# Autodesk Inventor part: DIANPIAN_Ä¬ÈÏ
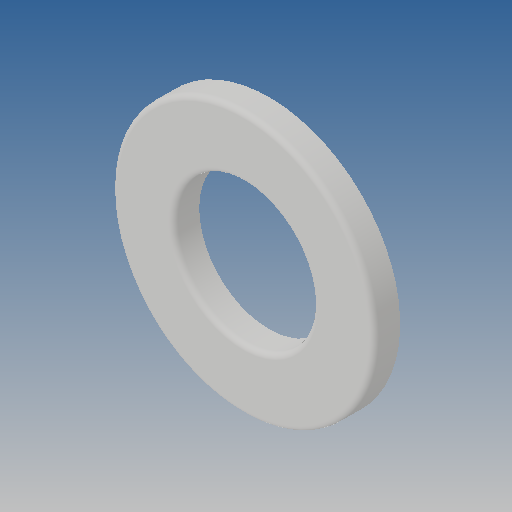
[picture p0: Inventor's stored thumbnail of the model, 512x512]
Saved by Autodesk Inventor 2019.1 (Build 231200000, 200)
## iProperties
Created: 2010-06
Part Number: DIANPIAN_Ä¬ÈÏ
Material: Ogólny
Document SubType Name: Modeling
Designer: CADENGINEERING4
Density: 1 g/cm^3
Appearance: Domyślna
Author: CADENGINEERING4
Revision Number: ÈÎºÎ
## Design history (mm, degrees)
feature "NONE"
node "Bryła1"
